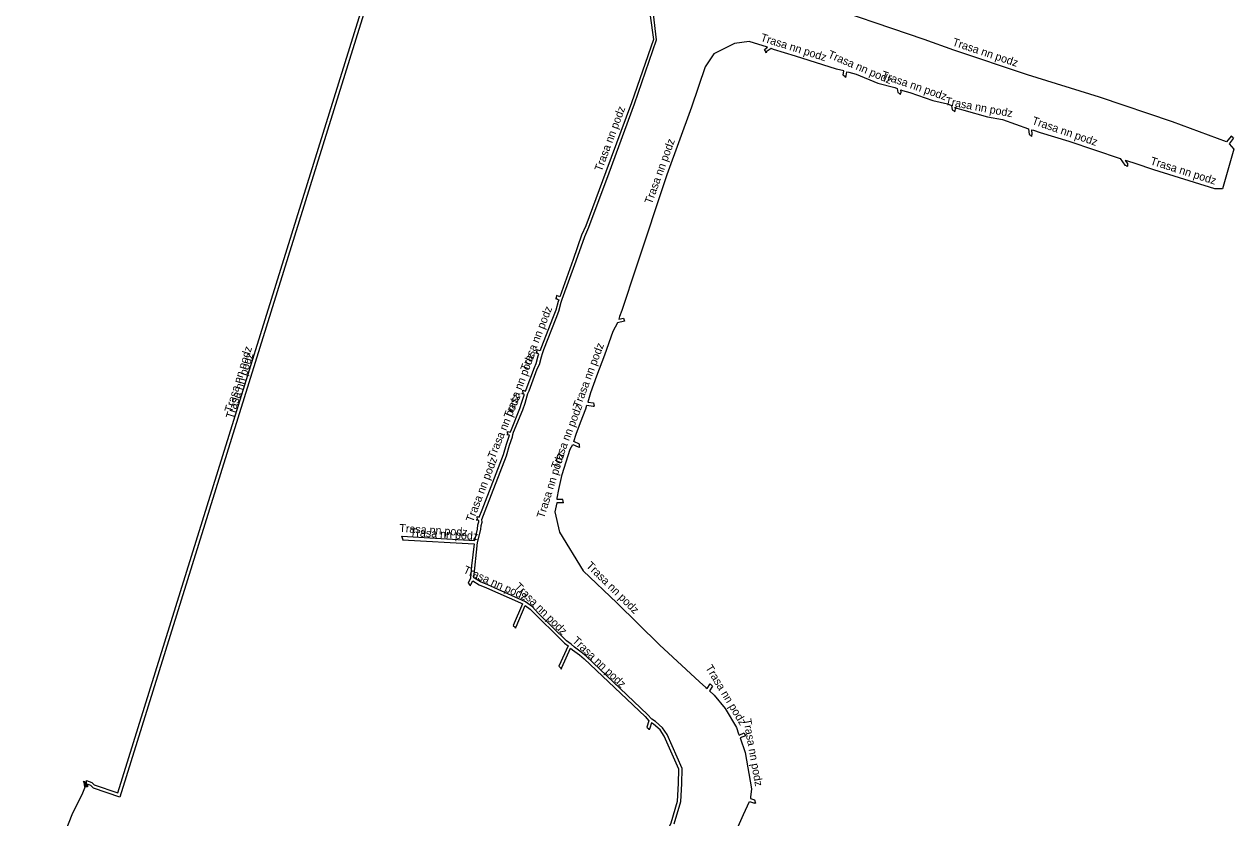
# Model space of a CAD drawing. Extents: x -742082 to -717476, y -1040737 to -1024597.
# Drawn here: x -735648.8 to -735497.7, y -1032436.2 to -1032337.1 of the extents above; entities that cross this region are included whole.
import ezdxf

# ---------------------------------------------------------------- set-up
doc = ezdxf.new("R2010")
doc.units = 0
for name, color, linetype in [('Level 15', 7, 'Continuous'), ('Level 20', 7, 'Continuous'), ('Level 25', 7, 'Continuous')]:
    doc.layers.add(name, color=color, linetype=linetype)

msp = doc.modelspace()

# ---------------------------------------------------------------- linework, layer by layer
at = {"layer": 'Level 15'}
for points in [[(-735602.42, -1032322.25), (-735602.56, -1032322.76), (-735602.51, -1032323.16), (-735636.87, -1032433.66), (-735640.16, -1032432.53), (-735640.5, -1032432.2), (-735640.94, -1032432.05), (-735640.94, -1032432.36), (-735641.26, -1032432.36), (-735641.33, -1032431.81)], [(-735641.31, -1032431.81), (-735641.23, -1032432.26), (-735641.04, -1032432.26), (-735641.04, -1032431.6), (-735640.37, -1032431.82), (-735640.07, -1032432.14), (-735637.13, -1032433.14), (-735602.88, -1032323), (-735604, -1032322.4), (-735603.92, -1032321.8)], [(-735577.78, -1032332.87), (-735577.78, -1032332.91), (-735577.68, -1032332.69), (-735577.63, -1032332.11), (-735577.52, -1032332.13), (-735576.52, -1032332.44), (-735572.98, -1032333.83), (-735570.62, -1032336.06), (-735570.24, -1032339.03), (-735572.96, -1032346.92), (-735576.16, -1032355.55), (-735578.67, -1032362.3), (-735579.2, -1032363.46), (-735580.26, -1032366.52), (-735581.93, -1032371.15), (-735582.34, -1032371.01), (-735582.39, -1032371.24), (-735582.31, -1032371.4)], [(-735497.8, -1032351.29), (-735498.05, -1032351.08), (-735498.64, -1032351.82), (-735505.4, -1032349.31), (-735514.51, -1032346.22), (-735523.51, -1032343.43), (-735532.72, -1032340.36), (-735536.42, -1032339.02), (-735550.62, -1032334.2), (-735554.38, -1032332.77), (-735555.92, -1032332.26), (-735555.62, -1032331.68), (-735555.51, -1032331.86), (-735555.44, -1032331.77)], [(-735556.17, -1032340.61), (-735556.38, -1032340.25), (-735555.99, -1032339.97), (-735558.28, -1032339.27), (-735560.12, -1032339.54), (-735562.69, -1032340.81), (-735563.78, -1032342.45), (-735565.49, -1032347.46), (-735568.55, -1032355.91), (-735572.41, -1032367.46), (-735574.2, -1032372.89), (-735574.47, -1032373.64), (-735574.55, -1032373.96), (-735573.98, -1032373.81), (-735573.83, -1032374.2)], [(-735546.25, -1032343.71), (-735546.55, -1032343.48), (-735546.47, -1032342.94), (-735547.36, -1032342.73), (-735552.48, -1032341.11), (-735555.24, -1032340.26), (-735555.53, -1032340.14), (-735556.16, -1032340.57), (-735556.1, -1032340.65), (-735556.23, -1032340.68), (-735556.17, -1032340.61)], [(-735546.25, -1032343.71), (-735546.23, -1032343.77), (-735546.15, -1032343.54), (-735546.08, -1032343.04), (-735545.81, -1032343.1), (-735544.89, -1032343.34), (-735542.21, -1032344.49), (-735540.07, -1032345.03), (-735539.78, -1032345.16), (-735539.7, -1032345.64), (-735539.4, -1032345.81)], [(-735539.4, -1032345.81), (-735539.4, -1032345.88), (-735539.3, -1032345.58), (-735539.35, -1032345.31), (-735539.11, -1032345.38), (-735538.19, -1032345.64), (-735535.32, -1032346.63), (-735533.5, -1032347.04), (-735532.99, -1032347.27), (-735532.91, -1032347.8), (-735532.61, -1032347.97)], [(-735532.61, -1032347.97), (-735532.6, -1032348.04), (-735532.51, -1032347.74), (-735532.55, -1032347.47), (-735532.32, -1032347.59), (-735531.47, -1032347.85), (-735528.49, -1032348.68), (-735526.63, -1032349.03), (-735523.4, -1032350.16), (-735523.32, -1032350.88), (-735523.02, -1032351.06)], [(-735523.02, -1032351.06), (-735523.02, -1032351.13), (-735522.92, -1032350.84), (-735522.98, -1032350.29), (-735522.78, -1032350.35), (-735521.92, -1032350.62), (-735518.33, -1032351.7), (-735511.95, -1032353.9), (-735511.34, -1032354.73), (-735511.08, -1032354.81)], [(-735497.77, -1032351.29), (-735497.8, -1032351.38), (-735498.31, -1032352.05), (-735497.74, -1032352.71), (-735499.14, -1032357.67), (-735500.11, -1032357.69), (-735507.72, -1032355.29), (-735510.07, -1032354.52), (-735510.98, -1032354.21), (-735511.29, -1032354.12), (-735511.02, -1032354.49), (-735511, -1032354.84), (-735511.1, -1032354.88), (-735511.08, -1032354.81)], [(-735582.31, -1032371.4), (-735582.47, -1032371.39), (-735582.06, -1032371.53), (-735582.12, -1032371.74), (-735582.41, -1032372.82), (-735582.75, -1032373.68), (-735584.29, -1032377.62), (-735584.4, -1032377.93), (-735584.79, -1032377.79), (-735584.82, -1032378.03), (-735584.76, -1032378.17)], [(-735573.83, -1032374.2), (-735574.74, -1032374.42), (-735575.31, -1032375.51), (-735576.34, -1032378.44), (-735577.33, -1032381.07), (-735578.08, -1032383.17), (-735578.43, -1032384.33), (-735577.71, -1032384.42), (-735577.64, -1032384.82)], [(-735586.52, -1032383.23), (-735586.56, -1032382.84), (-735586.22, -1032382.94), (-735586.12, -1032382.74), (-735585.1, -1032380.01), (-735584.86, -1032379.49), (-735584.61, -1032378.55), (-735584.53, -1032378.31), (-735584.93, -1032378.16), (-735584.76, -1032378.17)], [(-735588.4, -1032388.38), (-735588.45, -1032387.99), (-735588.12, -1032388.07), (-735588.06, -1032387.93), (-735586.91, -1032385.12), (-735586.65, -1032384.34), (-735586.38, -1032383.44), (-735586.36, -1032383.32), (-735586.68, -1032383.22), (-735586.52, -1032383.23)], [(-735579.44, -1032389.93), (-735579.48, -1032389.78), (-735579.45, -1032389.55), (-735580.16, -1032389.22), (-735579.89, -1032388.32), (-735579.34, -1032386.88), (-735578.67, -1032385.17), (-735578.55, -1032384.71), (-735577.77, -1032384.82), (-735577.64, -1032384.82)], [(-735592.21, -1032399.01), (-735592.25, -1032398.61), (-735591.98, -1032398.7), (-735591.62, -1032397.77), (-735588.98, -1032390.88), (-735588.58, -1032389.56), (-735588.24, -1032388.58), (-735588.22, -1032388.45), (-735588.55, -1032388.38), (-735588.4, -1032388.38)], [(-735581.45, -1032396.88), (-735581.55, -1032396.48), (-735582.25, -1032396.49), (-735582.27, -1032396.31), (-735582.05, -1032395.22), (-735581.63, -1032393.37), (-735580.62, -1032390.18), (-735580.31, -1032389.59), (-735579.62, -1032389.91), (-735579.44, -1032389.93)], [(-735581.45, -1032396.88), (-735582.28, -1032396.89), (-735582.54, -1032398.04), (-735581.96, -1032400.57), (-735579.01, -1032405.41), (-735574.81, -1032409.37), (-735569.47, -1032414.63), (-735564.49, -1032419.26), (-735563.68, -1032419.95), (-735563.52, -1032420.1), (-735563.13, -1032419.5), (-735562.86, -1032419.81)], [(-735601.55, -1032401.45), (-735601.64, -1032401.05), (-735592.56, -1032401.62), (-735592.19, -1032400.18), (-735592.15, -1032399.65), (-735592.03, -1032399.27), (-735592.05, -1032399.1), (-735592.38, -1032399), (-735592.21, -1032399.01)], [(-735601.55, -1032401.45), (-735601.57, -1032401.5), (-735592.64, -1032402.02), (-735592.97, -1032404.75), (-735593.07, -1032406.3), (-735593.39, -1032406.92), (-735593.11, -1032407.21)], [(-735593.11, -1032407.21), (-735593.1, -1032407.26), (-735593.03, -1032407.1), (-735592.79, -1032406.64), (-735592.02, -1032407.13), (-735591.07, -1032407.5), (-735586.84, -1032409.4), (-735586.6, -1032409.52), (-735587.75, -1032412.21), (-735587.46, -1032412.49)], [(-735587.46, -1032412.49), (-735587.46, -1032412.57), (-735587.38, -1032412.37), (-735586.25, -1032409.74), (-735585.61, -1032410.2), (-735581.35, -1032414.43), (-735580.9, -1032414.78), (-735582.06, -1032417.3), (-735581.77, -1032417.59)], [(-735581.77, -1032417.59), (-735581.77, -1032417.66), (-735581.69, -1032417.47), (-735580.58, -1032415.05), (-735580.34, -1032415.26), (-735579.48, -1032415.87), (-735578.89, -1032416.37), (-735571.25, -1032423.6), (-735570.79, -1032424.13), (-735571.07, -1032424.91), (-735570.78, -1032425.18)], [(-735562.86, -1032419.81), (-735563.22, -1032420.38), (-735562.66, -1032420.93), (-735561.28, -1032422.6), (-735559.86, -1032424.95), (-735559.62, -1032425.77), (-735559.54, -1032425.91), (-735558.9, -1032425.64), (-735558.72, -1032426.02)], [(-735580.8, -1032466.22), (-735580.89, -1032466.09), (-735580.86, -1032465.83), (-735580.63, -1032465.88), (-735579.34, -1032462.85), (-735577.74, -1032458.54), (-735574.83, -1032452.56), (-735570.78, -1032442.79), (-735568.02, -1032436.87), (-735567.23, -1032434.16), (-735567.1, -1032431.97), (-735567.05, -1032430.18), (-735568.89, -1032426.04), (-735569.41, -1032425.26), (-735570.22, -1032424.54), (-735570.46, -1032424.39), (-735570.69, -1032425.05), (-735570.78, -1032425.25), (-735570.78, -1032425.18)], [(-735558.72, -1032426.02), (-735559.38, -1032426.27), (-735558.79, -1032428.1), (-735557.98, -1032432.62), (-735558.1, -1032433.68), (-735558.12, -1032433.81), (-735557.61, -1032434), (-735557.5, -1032434.43), (-735557.61, -1032434.45), (-735557.58, -1032434.39)], [(-735641.28, -1032431.81), (-735641.27, -1032431.87), (-735641.23, -1032431.74), (-735641.48, -1032431.72), (-735641.12, -1032432.11), (-735641.54, -1032433.15), (-735642.86, -1032435.87), (-735646.14, -1032444.16), (-735648.4, -1032449.19), (-735648.79, -1032449.63), (-735648.83, -1032449.74)], [(-735563.47, -1032448.29), (-735563.5, -1032448.35), (-735563.39, -1032448.33), (-735563.49, -1032447.91), (-735564.04, -1032447.67), (-735564.02, -1032447.54), (-735563.63, -1032446.62), (-735563.42, -1032445.88), (-735558.97, -1032435.81), (-735558.24, -1032434.19), (-735557.75, -1032434.38), (-735557.58, -1032434.39)]]:
    msp.add_lwpolyline(points, dxfattribs=at)
at = {"layer": 'Level 25'}
for points in [[(-735578.82, -1032363.61), (-735578.3, -1032362.46), (-735575.78, -1032355.69), (-735572.58, -1032347.06), (-735569.84, -1032339.07), (-735570.24, -1032335.86)], [(-735567.64, -1032436.99), (-735566.83, -1032434.22), (-735566.7, -1032432), (-735566.65, -1032430.1), (-735568.53, -1032425.84), (-735569.11, -1032425), (-735569.98, -1032424.22), (-735570.43, -1032423.94), (-735570.97, -1032423.32), (-735578.63, -1032416.07), (-735579.24, -1032415.55), (-735580.1, -1032414.94), (-735580.52, -1032414.57), (-735581.09, -1032414.13), (-735584.61, -1032410.69), (-735585.35, -1032409.89), (-735586.23, -1032409.26), (-735586.66, -1032409.04), (-735590.91, -1032407.14), (-735591.84, -1032406.77), (-735592.58, -1032406.3), (-735592.66, -1032406.25), (-735592.21, -1032401.86), (-735591.79, -1032400.24), (-735591.75, -1032399.73), (-735591.63, -1032399.31), (-735591.66, -1032398.98), (-735591.24, -1032397.91), (-735588.6, -1032391.01), (-735588.2, -1032389.68), (-735587.84, -1032388.66), (-735587.81, -1032388.35), (-735587.7, -1032388.09), (-735586.53, -1032385.26), (-735586.27, -1032384.46), (-735586, -1032383.54), (-735585.93, -1032383.25), (-735585.76, -1032382.9), (-735584.74, -1032380.17), (-735584.48, -1032379.63), (-735584.23, -1032378.67), (-735584.09, -1032378.26), (-735583.91, -1032377.76), (-735582.37, -1032373.82), (-735582.03, -1032372.94), (-735581.74, -1032371.85), (-735581.62, -1032371.46), (-735579.88, -1032366.66), (-735578.82, -1032363.61)]]:
    msp.add_lwpolyline(points, dxfattribs=at)

# ---------------------------------------------------------------- texts
at = {"layer": 'Level 20'}
for rotation, p in [(342.4423, (-735556.93, -1032339.18)), (341.5651, (-735532.98, -1032339.74)), (336.7756, (-735548.53, -1032341.24)), (340.9682, (-735541.85, -1032343.85)), (349.3432, (-735533.85, -1032347.16)), (69.6509, (-735576.7, -1032355.58)), (341.0037, (-735523.04, -1032349.55)), (70.0931, (-735570.44, -1032359.66)), (342.4961, (-735508.25, -1032354.6)), (68.6535, (-735585.96, -1032380.53)), (72.7257, (-735622.89, -1032385.68)), (69.3724, (-735579.39, -1032385.13)), (72.726, (-735622.72, -1032386.48)), (69.4992, (-735588.03, -1032386.42)), (67.6383, (-735590.06, -1032391.46)), (69.0959, (-735582.13, -1032392.77)), (72.4315, (-735583.9, -1032398.9)), (69.0578, (-735592.77, -1032399.39)), (356.406, (-735602, -1032400.53)), (356.6738, (-735600.68, -1032401.05)), (335.8618, (-735594.07, -1032405.61)), (315.4324, (-735578.7, -1032404.84)), (315.2026, (-735587.66, -1032407.46)), (316.5794, (-735580.44, -1032414.22)), (301.1427, (-735563.78, -1032417.49)), (280.1598, (-735559.02, -1032423.95))]:
    msp.add_text('Trasa nn podz', height=1, rotation=rotation, dxfattribs=at).set_placement(p)

doc.saveas('drawing.dxf')
